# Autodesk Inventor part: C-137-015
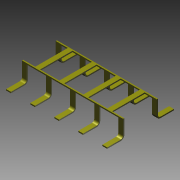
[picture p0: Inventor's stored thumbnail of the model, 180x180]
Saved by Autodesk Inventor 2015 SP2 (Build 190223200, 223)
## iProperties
Category: PARTsolutions
Company: SAMTEC
Created: 2015-08
Part Number: C-137-015
Catalog Web Link: www.cadenas.de
Description: SSM Series Terminal-SSM Series - (2,54 mm) .100" Tiger Claw™ Surface Mount Socket
Vendor: SAMTEC
Document SubType Name: Modeling
Designer: PARTuser1
Manufacturer: SAMTEC
Mass: 0.00336975 g
Surface Area: 0.699466 cm^2
Volume: 0.00336975 cm^3
Density: 1 g/cm^3
Material: Allgemein
Appearance: PSOLRGB-255-255-0
PSOL_IDENT_0: {$CADENAS_DATA\23d-libs\samtec\modelling\ssm\parts\ssm_terminal.prj},176 {VTYP=3D},{NB=C-137-015},{L
PSOL_IDENT_1: INA=C-137-015},{NN=SSM Series Terminal},{DATE=25.05.2015 11:25:09},{GEOMDATE=25.05.2015 11:24:00},{V
PSOL_IDENT_2: ERSION=},{LINEID=40},{LINESUBID=-1},{WBVAR=POS}  {NB=C-137-015},{LINA=C-137-015},{KT=DUMMY},{PN=C-13
PSOL_IDENT_3: 7-01},{ROW=-DV},{POS=5}
NN: SSM Series Terminal
NT: SSM Series - (2,54 mm) .100" Tiger Claw™ Surface Mount Socket
NB: C-137-015
NBSYN: $PN.$POS.
LINA: C-137-015
PN: C-137-01
ROW: -DV
POS: 5
SUPPLIER: SAMTEC
ARTICLENO: C-137-015
BOMINFO: C-137-015
CREATOR: CADENAS GmbH
Title: C-137-015
Author: Cadenas PARTsolutions
Comments: SSM Series - (2,54 mm) .100" Tiger Claw™ Surface Mount Socket
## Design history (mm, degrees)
sketch "Sketch_1"
  geometry: L1 (0.127, 3.518)-(0, 3.518); L2 (0, 3.518)-(0, 2.096); L3 (0.381, 1.714)-(1.778, 1.714); L4 (1.778, 1.714)-(1.778, -1.714); L5 (1.778, -1.714)-(0.381, -1.714); L6 (0, -2.096)-(0, -3.518); L7 (0, -3.518)-(0.127, -3.518); L8 (0.127, -3.518)-(0.127, -2.096); L9 (0.381, -1.842)-(1.905, -1.842); L10 (1.905, -1.842)-(1.905, 1.842); L11 (1.905, 1.842)-(0.381, 1.842); L12 (0.127, 2.096)-(0.127, 3.518); A1 r 0.381 centre (0.381, 2.095) between (0, 2.096) and (0.381, 1.714); A2 r 0.381 centre (0.381, -2.095) between (0.381, -1.714) and (0, -2.096); A3 r 0.254 centre (0.381, -2.095) between (0.381, -1.842) and (0.127, -2.096); A4 r 0.254 centre (0.381, 2.095) between (0.127, 2.096) and (0.381, 1.842)
  constraints: 24 end point, 8 point on circle, 4 centre point
extrude "Extrusion1" join sketch "Sketch_1" stored distance "d0" = 10.668; taper "d1" = 0 deg
sketch "Sketch_2"
  geometry: L1 (-6.096, 2.413)-(-6.096, 0); L2 (-6.096, 0)-(-4.064, 0); L3 (-4.064, 0)-(-4.064, 1.905); L4 (-4.064, 1.905)-(-3.556, 1.905); L5 (-3.556, 1.905)-(-3.556, 0); L6 (-3.556, 0)-(-1.524, 0); L7 (-1.524, 0)-(-1.524, 1.905); L8 (-1.524, 1.905)-(-1.016, 1.905); L9 (-1.016, 1.905)-(-1.016, 0); L10 (-1.016, 0)-(1.016, 0); L11 (1.016, 0)-(1.016, 1.905); L12 (1.016, 1.905)-(1.524, 1.905); L13 (1.524, 1.905)-(1.524, 0); L14 (1.524, 0)-(3.556, 0); L15 (3.556, 0)-(3.556, 1.905); L16 (3.556, 1.905)-(4.064, 1.905); L17 (4.064, 1.905)-(4.064, 0); L18 (4.064, 0)-(6.096, 0); L19 (6.096, 0)-(6.096, 1.905); L20 (6.096, 1.905)-(6.604, 1.905); L21 (6.604, 1.905)-(6.604, 0); L22 (6.604, 0)-(8.636, 0); L23 (8.636, 0)-(8.636, 1.905); L24 (8.636, 1.905)-(9.144, 1.905); L25 (9.144, 1.905)-(9.144, 0); L26 (9.144, 0)-(11.176, 0); L27 (11.176, 0)-(11.176, 1.905); L28 (11.176, 1.905)-(11.684, 1.905); L29 (11.684, 1.905)-(11.684, 0); L30 (11.684, 0)-(13.716, 0); L31 (13.716, 0)-(13.716, 1.905); L32 (13.716, 1.905)-(14.224, 1.905); L33 (14.224, 1.905)-(14.224, 0); L34 (14.224, 0)-(16.256, 0); L35 (16.256, 0)-(16.256, 1.905); L36 (16.256, 1.905)-(16.764, 1.905); L37 (16.764, 1.905)-(16.764, 0); L38 (16.764, 0)-(18.796, 0); L39 (18.796, 0)-(18.796, 1.905); L40 (18.796, 1.905)-(19.304, 1.905); L41 (19.304, 1.905)-(19.304, 0); L42 (19.304, 0)-(21.336, 0); L43 (21.336, 0)-(21.336, 1.905); L44 (21.336, 1.905)-(21.844, 1.905); L45 (21.844, 1.905)-(21.844, 0); L46 (21.844, 0)-(23.876, 0); L47 (23.876, 0)-(23.876, 1.905); L48 (23.876, 1.905)-(24.384, 1.905); L49 (24.384, 1.905)-(24.384, 0); L50 (24.384, 0)-(26.416, 0); L51 (26.416, 0)-(26.416, 1.905); L52 (26.416, 1.905)-(26.924, 1.905); L53 (26.924, 1.905)-(26.924, 0); L54 (26.924, 0)-(28.956, 0); L55 (28.956, 0)-(28.956, 1.905); L56 (28.956, 1.905)-(29.464, 1.905); L57 (29.464, 1.905)-(29.464, 0); L58 (29.464, 0)-(31.496, 0); L59 (31.496, 0)-(31.496, 1.905); L60 (31.496, 1.905)-(32.004, 1.905); L61 (32.004, 1.905)-(32.004, 0); L62 (32.004, 0)-(34.036, 0); L63 (34.036, 0)-(34.036, 1.905); L64 (34.036, 1.905)-(34.544, 1.905)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
  constraints: 328 end point
extrude "Extrusion2" cut sketch "Sketch_2" stored distance "d2" = 3.429; taper "d3" = 0 deg
sketch "Sketch_4"
  geometry: L1 (-4.826, -0.508)-(98.806, -0.508); L2 (98.806, -0.508)-(98.806, 1.778); L3 (98.806, 1.778)-(96.774, 1.778); L4 (96.774, 1.778)-(96.774, 0); L5 (96.774, 0)-(96.266, 0); L6 (96.266, 0)-(96.266, 1.778); L7 (96.266, 1.778)-(94.234, 1.778); L8 (94.234, 1.778)-(94.234, 0); L9 (94.234, 0)-(93.726, 0); L10 (93.726, 0)-(93.726, 1.778); L11 (93.726, 1.778)-(91.694, 1.778); L12 (91.694, 1.778)-(91.694, 0); L13 (91.694, 0)-(91.186, 0); L14 (91.186, 0)-(91.186, 1.778); L15 (91.186, 1.778)-(89.154, 1.778); L16 (89.154, 1.778)-(89.154, 0); L17 (89.154, 0)-(88.646, 0); L18 (88.646, 0)-(88.646, 1.778); L19 (88.646, 1.778)-(86.614, 1.778); L20 (86.614, 1.778)-(86.614, 0); L21 (86.614, 0)-(86.106, 0); L22 (86.106, 0)-(86.106, 1.778); L23 (86.106, 1.778)-(84.074, 1.778); L24 (84.074, 1.778)-(84.074, 0); L25 (84.074, 0)-(83.566, 0); L26 (83.566, 0)-(83.566, 1.778); L27 (83.566, 1.778)-(81.534, 1.778); L28 (81.534, 1.778)-(81.534, 0); L29 (81.534, 0)-(81.026, 0); L30 (81.026, 0)-(81.026, 1.778); L31 (81.026, 1.778)-(78.994, 1.778); L32 (78.994, 1.778)-(78.994, 0); L33 (78.994, 0)-(78.486, 0); L34 (78.486, 0)-(78.486, 1.778); L35 (78.486, 1.778)-(76.454, 1.778); L36 (76.454, 1.778)-(76.454, 0); L37 (76.454, 0)-(75.946, 0); L38 (75.946, 0)-(75.946, 1.778); L39 (75.946, 1.778)-(73.914, 1.778); L40 (73.914, 1.778)-(73.914, 0); L41 (73.914, 0)-(73.406, 0); L42 (73.406, 0)-(73.406, 1.778); L43 (73.406, 1.778)-(71.374, 1.778); L44 (71.374, 1.778)-(71.374, 0); L45 (71.374, 0)-(70.866, 0); L46 (70.866, 0)-(70.866, 1.778); L47 (70.866, 1.778)-(68.834, 1.778); L48 (68.834, 1.778)-(68.834, 0); L49 (68.834, 0)-(68.326, 0); L50 (68.326, 0)-(68.326, 1.778); L51 (68.326, 1.778)-(66.294, 1.778); L52 (66.294, 1.778)-(66.294, 0); L53 (66.294, 0)-(65.786, 0); L54 (65.786, 0)-(65.786, 1.778); L55 (65.786, 1.778)-(63.754, 1.778); L56 (63.754, 1.778)-(63.754, 0); L57 (63.754, 0)-(63.246, 0); L58 (63.246, 0)-(63.246, 1.778); L59 (63.246, 1.778)-(61.214, 1.778); L60 (61.214, 1.778)-(61.214, 0); L61 (61.214, 0)-(60.706, 0); L62 (60.706, 0)-(60.706, 1.778); L63 (60.706, 1.778)-(58.674, 1.778); L64 (58.674, 1.778)-(58.674, 0)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
  constraints: 328 end point
extrude "Extrusion3" cut sketch "Sketch_4" stored distance "d4" = 10.16; taper "d5" = 0 deg
node "terminal_XY"
node "terminal_YZ"
node "terminal_ZX"
node "terminal_X"
node "terminal_Y"
node "terminal_Z"
node "terminal_Center"
body "Solid1"
